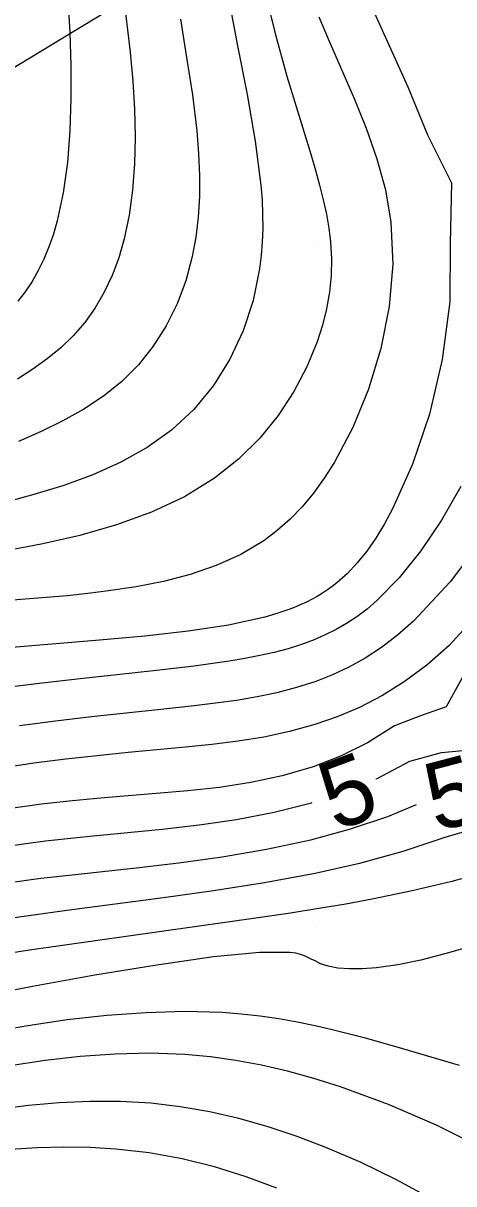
# Model space of a CAD drawing. Extents: x 2602990 to 2605851, y 618069 to 619180.
# Drawn here: x 2603391.43 to 2603404.07, y 618642.47 to 618676.53 of the extents above; entities that cross this region are included whole.
import ezdxf

# ---------------------------------------------------------------- set-up
doc = ezdxf.new("R2010")
doc.units = 0
for name, color, linetype in [('DTM Contours Major', 7, 'Continuous'), ('DTM Contours Minor', 7, 'Continuous'), ('DTM Contours Minor Text', 7, 'Continuous'), ('Exist DTM Crownline', 7, 'Continuous'), ('Exist DTM QL2 LIDAR Elevation Point', 7, 'Continuous'), ('Exist Roads EOP', 7, 'Continuous'), ('PH Exist DTM Obscure Area', 7, 'Continuous')]:
    doc.layers.add(name, color=color, linetype=linetype)

msp = doc.modelspace()

# ---------------------------------------------------------------- linework, layer by layer
at = {"layer": 'DTM Contours Major'}
for points in [[(2603400.114, 618676.715), (2603400.411, 618675.997), (2603401.15, 618674.311), (2603401.504, 618673.441), (2603401.818, 618672.549), (2603402.067, 618671.633), (2603402.228, 618670.688), (2603402.281, 618669.459), (2603402.177, 618668.212), (2603401.934, 618666.976), (2603401.573, 618665.782), (2603401.111, 618664.66), (2603400.569, 618663.64), (2603400.27, 618663.171), (2603399.953, 618662.736), (2603399.618, 618662.334), (2603399.264, 618661.968), (2603398.889, 618661.635), (2603398.492, 618661.337), (2603397.817, 618660.934), (2603397.094, 618660.607), (2603396.334, 618660.347), (2603395.547, 618660.143), (2603394.743, 618659.985), (2603393.933, 618659.863), (2603393.326, 618659.788), (2603392.719, 618659.725), (2603392.108, 618659.67), (2603390.865, 618659.575)], [(2603399.255, 618649.255), (2603398.363, 618649.256), (2603397.015, 618649.122), (2603395.357, 618648.887), (2603393.537, 618648.585), (2603391.702, 618648.252), (2603390, 618647.92)], [(2603404.531, 618649.417), (2603403.813, 618649.21), (2603403.11, 618649.031), (2603402.435, 618648.89), (2603401.803, 618648.8), (2603401.387, 618648.771), (2603401.007, 618648.771), (2603400.671, 618648.798), (2603400.386, 618648.848), (2603400.16, 618648.921), (2603400, 618649.013), (2603399.889, 618649.059), (2603399.688, 618649.153), (2603399.573, 618649.196), (2603399.433, 618649.231), (2603399.255, 618649.255)]]:
    msp.add_lwpolyline(points, dxfattribs=at)
at = {"layer": 'DTM Contours Minor'}
for points in [[(2603398.517, 618677.508), (2603398.824, 618676.22), (2603399.174, 618674.974), (2603399.874, 618672.679), (2603400.01, 618672.217), (2603400.133, 618671.772), (2603400.24, 618671.34), (2603400.331, 618670.921), (2603400.402, 618670.512), (2603400.451, 618670.11), (2603400.479, 618669.611), (2603400.469, 618669.119), (2603400.422, 618668.631), (2603400.338, 618668.145), (2603400.217, 618667.66), (2603400.06, 618667.174), (2603399.759, 618666.444), (2603399.378, 618665.72), (2603398.917, 618665.017), (2603398.376, 618664.348), (2603397.754, 618663.728), (2603397.051, 618663.171), (2603396.164, 618662.63), (2603395.194, 618662.176), (2603394.164, 618661.8), (2603393.095, 618661.492), (2603392.008, 618661.242), (2603390.926, 618661.038)], [(2603397.45, 618677.322), (2603397.725, 618675.858), (2603398.003, 618674.436), (2603398.245, 618673.068), (2603398.41, 618671.772), (2603398.442, 618671.341), (2603398.46, 618670.92), (2603398.462, 618670.507), (2603398.448, 618670.102), (2603398.418, 618669.705), (2603398.37, 618669.313), (2603398.18, 618668.383), (2603397.888, 618667.496), (2603397.498, 618666.662), (2603397.014, 618665.891), (2603396.441, 618665.193), (2603395.781, 618664.578), (2603395.07, 618664.071), (2603394.297, 618663.64), (2603393.475, 618663.274), (2603392.618, 618662.961), (2603391.741, 618662.691), (2603390.856, 618662.452)], [(2603401.554, 618677.258), (2603402.113, 618675.994), (2603402.727, 618674.655), (2603403.3, 618673.246), (2603404.003, 618671.843), (2603403.967, 618670.072), (2603403.953, 618668.35), (2603403.736, 618666.659), (2603403.357, 618665.052), (2603402.861, 618663.58), (2603402.288, 618662.298), (2603402.04, 618661.836), (2603401.783, 618661.414), (2603401.518, 618661.031), (2603401.24, 618660.686), (2603400.95, 618660.377), (2603400.643, 618660.104), (2603400.505, 618659.995), (2603400.362, 618659.893), (2603400.216, 618659.796), (2603400.066, 618659.706), (2603399.911, 618659.62), (2603399.751, 618659.539), (2603399.564, 618659.454), (2603399.371, 618659.373), (2603399.17, 618659.298), (2603398.962, 618659.228), (2603398.747, 618659.162), (2603398.525, 618659.099), (2603397.458, 618658.864), (2603396.271, 618658.681), (2603394.998, 618658.536), (2603393.672, 618658.417), (2603390.992, 618658.199)], [(2603394.366, 618677.408), (2603394.565, 618675.679), (2603394.645, 618674.825), (2603394.696, 618673.999), (2603394.715, 618673.187), (2603394.699, 618672.395), (2603394.643, 618671.629), (2603394.544, 618670.894), (2603394.397, 618670.194), (2603394.237, 618669.644), (2603394.041, 618669.124), (2603393.808, 618668.633), (2603393.54, 618668.174), (2603393.235, 618667.746), (2603392.894, 618667.35), (2603392.53, 618666.999), (2603392.136, 618666.674), (2603391.713, 618666.369), (2603391.264, 618666.08)], [(2603392.76, 618676.887), (2603392.795, 618676.249), (2603392.828, 618675.289), (2603392.831, 618674.321), (2603392.799, 618673.364), (2603392.725, 618672.434), (2603392.603, 618671.549), (2603392.428, 618670.727), (2603392.315, 618670.332), (2603392.185, 618669.958), (2603392.038, 618669.602), (2603391.873, 618669.265), (2603391.689, 618668.946), (2603391.486, 618668.642), (2603391.271, 618668.364)], [(2603396.048, 618676.647), (2603396.229, 618675.518), (2603396.396, 618674.421), (2603396.526, 618673.365), (2603396.581, 618672.703), (2603396.608, 618672.061), (2603396.605, 618671.438), (2603396.57, 618670.833), (2603396.5, 618670.246), (2603396.394, 618669.675), (2603396.201, 618668.966), (2603395.946, 618668.289), (2603395.628, 618667.649), (2603395.25, 618667.051), (2603394.813, 618666.501), (2603394.317, 618666.004), (2603393.787, 618665.577), (2603393.211, 618665.196), (2603392.597, 618664.854), (2603391.953, 618664.542), (2603391.286, 618664.254)], [(2603401.787, 618654.349), (2603401.824, 618654.364), (2603402.778, 618654.864), (2603403.716, 618655.123), (2603404.639, 618655.211), (2603405.579, 618656.7), (2603407.264, 618659.209), (2603408.889, 618661.556), (2603410.445, 618663.877), (2603411.921, 618665.868), (2603413.301, 618667.226), (2603414.574, 618667.647), (2603415.834, 618666.788), (2603416.961, 618664.749), (2603417.967, 618661.845), (2603418.865, 618658.393), (2603419.669, 618654.708), (2603420.786, 618649.143), (2603421.043, 618647.9), (2603421.173, 618647.296), (2603421.652, 618645.213), (2603422.17, 618643.286), (2603422.75, 618641.54)], [(2603404.283, 618662.931), (2603403.709, 618661.937), (2603403.104, 618661.037), (2603402.473, 618660.245), (2603401.817, 618659.579), (2603401.525, 618659.331), (2603401.228, 618659.109), (2603400.926, 618658.909), (2603400.617, 618658.731), (2603400.301, 618658.572), (2603399.977, 618658.431), (2603399.597, 618658.29), (2603399.205, 618658.168), (2603398.798, 618658.06), (2603398.375, 618657.965), (2603397.935, 618657.881), (2603397.478, 618657.804), (2603396.445, 618657.657), (2603395.343, 618657.525), (2603393.01, 618657.275), (2603391.817, 618657.142), (2603390.632, 618656.993)], [(2603405.026, 618661.523), (2603403.971, 618660.13), (2603402.892, 618658.977), (2603402.419, 618658.564), (2603401.946, 618658.205), (2603401.47, 618657.895), (2603400.991, 618657.629), (2603400.507, 618657.402), (2603400.018, 618657.21), (2603399.455, 618657.028), (2603398.881, 618656.878), (2603398.295, 618656.755), (2603397.695, 618656.654), (2603397.079, 618656.567), (2603396.445, 618656.49), (2603395.472, 618656.382), (2603393.432, 618656.166), (2603392.38, 618656.046), (2603391.319, 618655.909)], [(2603405.476, 618659.946), (2603403.942, 618658.266), (2603403.278, 618657.685), (2603402.618, 618657.194), (2603401.961, 618656.784), (2603401.306, 618656.444), (2603400.651, 618656.166), (2603399.995, 618655.94), (2603399.248, 618655.736), (2603398.496, 618655.577), (2603397.738, 618655.453), (2603396.971, 618655.356), (2603396.195, 618655.276), (2603394.512, 618655.121), (2603393.601, 618655.03), (2603392.676, 618654.928), (2603391.737, 618654.809), (2603390.785, 618654.667)], [(2603404.69, 618657.993), (2603403.848, 618656.46), (2603403.095, 618656.198), (2603402.336, 618655.904), (2603401.543, 618655.407), (2603400.747, 618655.013), (2603399.947, 618654.703), (2603399.035, 618654.436), (2603398.117, 618654.239), (2603397.194, 618654.098), (2603396.265, 618653.996), (2603395.333, 618653.917), (2603394.396, 618653.845), (2603393.591, 618653.777), (2603392.782, 618653.699), (2603391.964, 618653.606), (2603391.137, 618653.494)], [(2603390.791, 618652.346), (2603391.435, 618652.442), (2603392.08, 618652.527), (2603392.73, 618652.603), (2603393.389, 618652.672), (2603395.509, 618652.875), (2603396.596, 618652.999), (2603397.693, 618653.158), (2603398.795, 618653.369), (2603399.896, 618653.648), (2603399.913, 618653.653)], [(2603391.039, 618651.309), (2603391.945, 618651.432), (2603392.415, 618651.489), (2603394.75, 618651.743), (2603395.996, 618651.889), (2603397.274, 618652.065), (2603398.572, 618652.285), (2603399.873, 618652.564), (2603401.013, 618652.87), (2603402.139, 618653.247), (2603402.975, 618653.6)], [(2603405.012, 618652.982), (2603403.814, 618652.629), (2603402.577, 618652.216), (2603401.303, 618651.869), (2603400.003, 618651.576), (2603398.513, 618651.297), (2603397.021, 618651.061), (2603395.546, 618650.856), (2603392.709, 618650.49), (2603391.169, 618650.271)], [(2603405.135, 618651.648), (2603404.013, 618651.337), (2603402.854, 618651.061), (2603401.672, 618650.818), (2603400.9, 618650.676), (2603400.108, 618650.542), (2603399.279, 618650.412), (2603398.396, 618650.282), (2603391.614, 618649.319), (2603390.663, 618649.18), (2603390, 618649.077)], [(2603404.242, 618645.938), (2603402.414, 618646.472), (2603401.48, 618646.736), (2603400.541, 618646.978), (2603400.007, 618647.1), (2603399.471, 618647.21), (2603398.932, 618647.304), (2603398.386, 618647.383), (2603397.834, 618647.445), (2603397.271, 618647.489), (2603396.169, 618647.52), (2603395.036, 618647.488), (2603393.884, 618647.403), (2603392.724, 618647.273), (2603391.568, 618647.105), (2603390.429, 618646.91)], [(2603405.004, 618643.477), (2603403.584, 618644.177), (2603402.153, 618644.791), (2603400.742, 618645.309), (2603399.959, 618645.557), (2603399.19, 618645.769), (2603398.43, 618645.947), (2603397.677, 618646.088), (2603396.926, 618646.194), (2603396.175, 618646.262), (2603395.154, 618646.298), (2603394.127, 618646.274), (2603393.099, 618646.199), (2603392.071, 618646.081), (2603391.048, 618645.928)], [(2603403.365, 618642.059), (2603402.375, 618642.592), (2603401.354, 618643.087), (2603400.316, 618643.535), (2603399.47, 618643.858), (2603398.619, 618644.141), (2603397.765, 618644.382), (2603396.906, 618644.579), (2603396.043, 618644.729), (2603395.175, 618644.83), (2603394.284, 618644.88), (2603393.389, 618644.881), (2603392.489, 618644.839), (2603391.586, 618644.759), (2603390.678, 618644.647), (2603389.767, 618644.509), (2603388.702, 618644.32), (2603387.641, 618644.11), (2603386.594, 618643.884), (2603385.568, 618643.649), (2603383.617, 618643.179), (2603381.842, 618642.747), (2603380.714, 618642.485), (2603379.734, 618642.273)], [(2603398.873, 618642.342), (2603397.974, 618642.675), (2603397.046, 618642.961), (2603396.095, 618643.194), (2603395.126, 618643.371), (2603394.147, 618643.487), (2603393.382, 618643.534), (2603392.613, 618643.545), (2603391.837, 618643.523), (2603391.053, 618643.472), (2603390.259, 618643.394), (2603389.454, 618643.293), (2603388.234, 618643.105), (2603387.006, 618642.882), (2603385.79, 618642.635), (2603384.607, 618642.373)]]:
    msp.add_lwpolyline(points, dxfattribs=at)
at = {"layer": 'Exist DTM Crownline'}
msp.add_spline([(2603233.488, 618380.754), (2603285.185, 618400.095), (2603335.457, 618418.629), (2603390.812, 618439.069), (2603440.087, 618457.325), (2603493.996, 618477.231), (2603542.655, 618495.301), (2603600.808, 618516.867), (2603653.659, 618536.362), (2603706.222, 618555.742), (2603764.811, 618577.593), (2603823.52, 618599.847), (2603878.564, 618620.56), (2603937.951, 618643.078), (2603997.369, 618665.789), (2604036.209, 618680.665), (2604055.311, 618688.017)], degree=3, dxfattribs=at)
at = {"layer": 'Exist DTM QL2 LIDAR Elevation Point'}
for p, q in [((2603400, 618670), (2603400, 618670)), ((2603400, 618660), (2603400, 618660)), ((2603400, 618650), (2603400, 618650))]:
    msp.add_line(p, q, dxfattribs=at)
at = {"layer": 'Exist Roads EOP'}
for points in [[(2603230.17, 618389.98), (2603282.929, 618409.597), (2603332.773, 618427.868), (2603388.167, 618448.413), (2603437.203, 618466.721), (2603490.778, 618486.527), (2603539.039, 618504.558), (2603597.451, 618526.156), (2603651.053, 618545.972), (2603705.208, 618566.084), (2603762.02, 618587.183), (2603820.334, 618609.162), (2603876.341, 618629.99), (2603934.909, 618652.28), (2603996.409, 618675.568), (2604033.216, 618689.957), (2604052.01, 618697.199)], [(2604034.633, 618668.486), (2603984.89, 618650.123), (2603936.767, 618631.654), (2603888.195, 618613.335), (2603837.766, 618594.258), (2603782.918, 618573.705), (2603731.939, 618554.39), (2603671.126, 618532.171), (2603621.822, 618514.106), (2603561.545, 618491.877), (2603506.421, 618471.293), (2603452.163, 618451.33), (2603398.364, 618431.316), (2603341.431, 618410.355), (2603281.65, 618388.199), (2603223.033, 618366.475), (2603185.717, 618352.612)]]:
    msp.add_spline(points, degree=3, dxfattribs=at)
at = {"layer": 'PH Exist DTM Obscure Area'}
msp.add_lwpolyline([(2603368.111, 618677.337), (2603381.679, 618675.114), (2603390.37, 618674.755), (2603398.261, 618679.54)], dxfattribs=at)

# ---------------------------------------------------------------- texts
at = {"layer": 'DTM Contours Minor Text'}
for rotation, p in [(20.3541, (2603400.599, 618652.8)), (14.6866, (2603403.542, 618652.787))]:
    msp.add_text('5', height=2, rotation=rotation, dxfattribs=at).set_placement(p)

doc.saveas('drawing.dxf')
